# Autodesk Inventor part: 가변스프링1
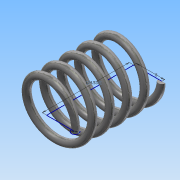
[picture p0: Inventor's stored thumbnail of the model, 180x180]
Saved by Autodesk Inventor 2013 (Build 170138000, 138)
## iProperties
Created: 2018-10
Part Number: 가변스프링1
Material: 스테인리스강
Document SubType Name: Modeling
Designer: Administrator
Density: 8.08 g/cm^3
Mass: 6.26693 g
Surface Area: 15.7633 cm^2
Volume: 0.77561 cm^3
Author: Administrator
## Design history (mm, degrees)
sketch "스케치1"
  geometry: L1 (0, 0)-(-8, 0); L2 (-8, 0)-(-8, 24.535); L3 (-8, 24.535)-(0, 24.535); C1 r 1 at (0, 0); 1 further point
  constraints: 6 end point, 1 centre point, 1 coincident, 1 horizontal, 1 parallel, 1 perpendicular, 1 vertical alignment
  dimensions: "d0" = 2 diameter of C1; "d2" = 24.53516 distance of L1.end L2.end (derived); "d3" = 8 distance of L2.end L3.end
feature "코일1" pitch "d4" = 10; turns "d6" = 5; dims "d5" = 24.53516 (= d2), "d7" = 0, angle "d8" = 90 deg, angle "d9" = 90 deg, "d10" = 0, "d11" = 0
sketch "스케치2"
  geometry: C1 r 22.863 at (0, 0); 1 further point
  constraints: 1 centre point, 1 coincident
extrude "돌출1" cut sketch "스케치2" distance "d12" = 10; taper "d13" = 0 deg
node "작업 평면1"
sketch "스케치3"
  geometry: C1 r 28.077 at (-8, 0); 1 further point
  constraints: 1 centre point, 1 coincident
extrude "돌출2" cut sketch "스케치3" distance "d14" = 10; taper "d15" = 0 deg
node "솔리드1"
